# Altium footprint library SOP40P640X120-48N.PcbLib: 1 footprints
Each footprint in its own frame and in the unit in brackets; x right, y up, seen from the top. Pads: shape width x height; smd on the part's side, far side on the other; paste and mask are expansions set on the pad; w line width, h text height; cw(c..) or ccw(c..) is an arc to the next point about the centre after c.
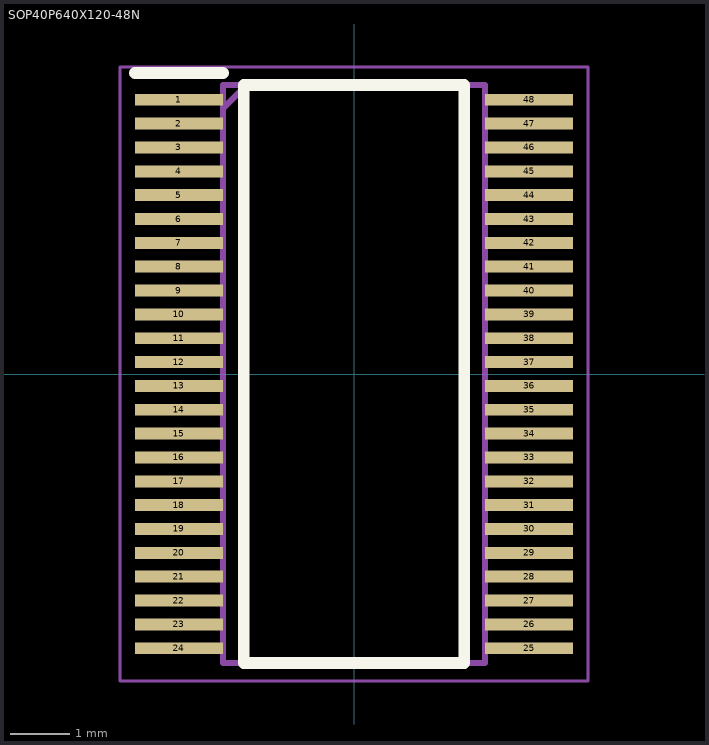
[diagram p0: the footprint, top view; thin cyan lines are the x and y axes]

## SOP40P640X120-48N [mm]
pads (48):
  rect 1.475x0.2 smd: 1(-2.938,4.6) 2(-2.938,4.2) 3(-2.938,3.8) 4(-2.938,3.4) 5(-2.938,3) 6(-2.938,2.6) 7(-2.938,2.2) 8(-2.938,1.8) 9(-2.938,1.4) 10(-2.938,1) 11(-2.938,0.6) 12(-2.938,0.2) 13(-2.938,-0.2) 14(-2.938,-0.6) 15(-2.938,-1) 16(-2.938,-1.4) 17(-2.938,-1.8) 18(-2.938,-2.2) 19(-2.938,-2.6) 20(-2.938,-3) 21(-2.938,-3.4) 22(-2.938,-3.8) 23(-2.938,-4.2) 24(-2.938,-4.6) 25(2.938,-4.6) 26(2.938,-4.2) 27(2.938,-3.8) 28(2.938,-3.4) 29(2.938,-3) 30(2.938,-2.6) 31(2.938,-2.2) 32(2.938,-1.8) 33(2.938,-1.4) 34(2.938,-1) 35(2.938,-0.6) 36(2.938,-0.2) 37(2.938,0.2) 38(2.938,0.6) 39(2.938,1) 40(2.938,1.4) 41(2.938,1.8) 42(2.938,2.2) 43(2.938,2.6) 44(2.938,3) 45(2.938,3.4) 46(2.938,3.8) 47(2.938,4.2) 48(2.938,4.6)
Top Overlay:
  lines w0.2: -3.675,5.05 -2.2,5.05 ; -1.85,-4.85 1.85,-4.85 1.85,4.85 -1.85,4.85 -1.85,-4.85
Mechanical 15:
  lines w0.1: -2.2,4.45 -1.8,4.85 ; -2.2,-4.85 2.2,-4.85 2.2,4.85 -2.2,4.85 -2.2,-4.85
Mechanical 20:
  lines w0.05: -3.925,-5.15 3.925,-5.15 3.925,5.15 -3.925,5.15 -3.925,-5.15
